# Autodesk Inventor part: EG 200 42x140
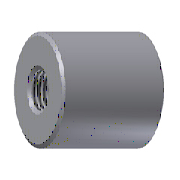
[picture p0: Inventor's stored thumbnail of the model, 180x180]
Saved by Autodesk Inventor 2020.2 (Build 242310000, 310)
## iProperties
Manager: www.cadconsulting.pl
Company: Fabian Stasiak CAD Consulting
Created: 2014-02
Part Number: EG 200 42x140
Material: DIN 1.7131
Description: Locating sleeves
Document SubType Name: Modeling
Designer: F.Stasiak
Standard Revision: 1
Manufacturer: DME
Language: pl-PL
Size Designation: 42x140
Categories: <MemberInstance><Categories><Category DisplayName="Forma wtryskowa" InternalName="349578f2-f4d4-4954-8c09-8e99297a61c0" Mnemonic="MOLD"><Category DisplayName="E
Mass: 1.68626 g
Surface Area: 16.3679 cm^2
Volume: 1.68626 cm^3
Density: 7.85 g/cm^3
Appearance: Stal
Catalog Web Link: www.expertbooks.pl
IsCustomPart: 0
Author: F.Stasiak
Subject: Zbiór ćwiczeń. Autodesk Inventor 2020. Kurs Professional
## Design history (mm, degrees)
sketch "Sketch1"
  geometry: L1 (0, -168)-(0, 28) reference; L2 (0, 0)-(21, 0); L3 (21, 0)-(21, -2.5); L4 (21, -2.5)-(20.987, -2.5); L5 (20.987, -2.5)-(20.988, -140); L6 (20.988, -140)-(16.5, -140); L7 (16.5, -140)-(16.5, -13); L8 (16.5, -13)-(8, -11); L9 (8, -11)-(0, -11); L10 (0, 0)-(0, -11); 1 further point
  constraints: 18 end point, 4 parallel, 3 perpendicular, 2 point on line, 1 coincident, 1 collinear
  dimensions: "d0" = 42 diameter of L3 L1 (= D); "d2" = 42 dimension on L5 L1 (= D_Guide); "d4" = 140 distance between parallel lines of L6 L2 (= L); "d5" = 33 diameter of L7 L1 (= d_); "d6" = 13 distance from line of L7.end L2 (= L1); "d7" = 2 distance from line of L7.end L9; "d8" = 16 diameter of L8.end L1 (= M); "d33" = 2.5 distance between parallel lines of L2 L4 (= L2)
revolve "Revolution1" sketch "Sketch1" stored, may be unused: angle "d9" = 90 deg
sketch "Sketch2"
  geometry: 1 further point
hole "Hole1" sketch "Sketch2" at (0, 0) diameter "d10" = 13.835; stored, may be unused: countersink angle "d14" = 90 deg, drill point angle "d16" = 0 deg; dims "d11" = 6, "d12" = 4, "d13" = 2, "d15" = 140 (= L)
chamfer "Chamfer1" distance "d17" = 0.5; stored, may be unused: second distance "d18" = 2, angle "d19" = 45 deg
fillet "Fillet1" dims "d30" = 0.5
body "Solid1"
other parameters: "D" = 42 [user parameter; used in 1 equation term], "L" = 140 [user parameter; used in 2 equation terms], "d_" = 33 [user parameter; used in 1 equation term], "M" = 16 [user parameter; used in 1 equation term], "L1" = 13 [user parameter; used in 1 equation term], "d22" = 0, "D_Guide" = 42 [user parameter; used in 1 equation term], "d31" = 0, "d32" = 0, "L2" = 2.5 [user parameter; used in 1 equation term]
